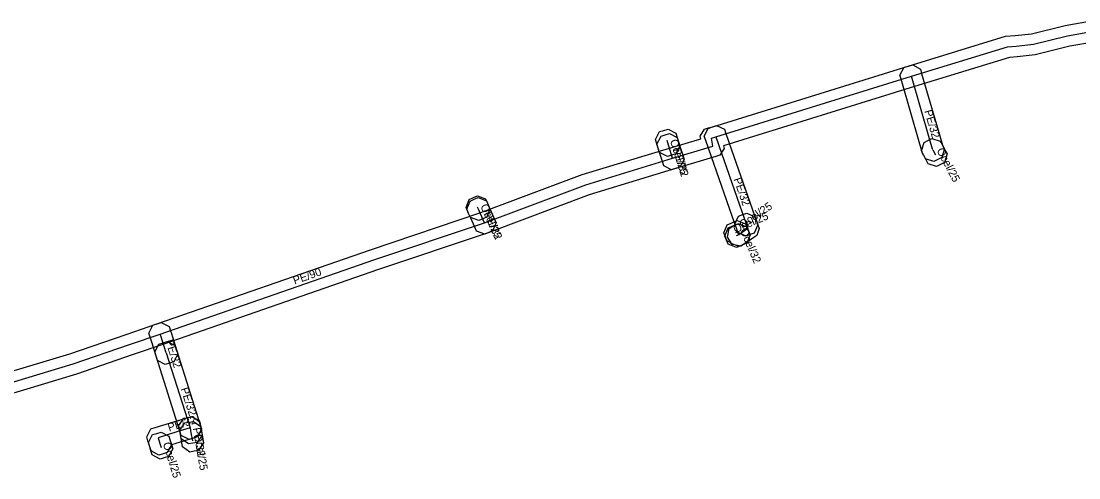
# Model space of a CAD drawing. Extents: x -677728 to -676939, y -1057290 to -1056960.
# Drawn here: x -677236.2 to -677137.1, y -1057070.2 to -1057027.4 of the extents above; entities that cross this region are included whole.
import ezdxf

# ---------------------------------------------------------------- set-up
doc = ezdxf.new("R2010")
doc.units = 0
for name, color, linetype in [('1', 7, 'Continuous'), ('24', 7, 'Continuous'), ('30', 7, 'Continuous')]:
    doc.layers.add(name, color=color, linetype=linetype)

msp = doc.modelspace()

# ---------------------------------------------------------------- linework, layer by layer
at = {"layer": '1'}
for points in [[(-677241.568, -1057061.585), (-677231.637, -1057058.588), (-677226.354, -1057056.778), (-677223.486, -1057055.795), (-677203.454, -1057048.844), (-677193.105, -1057045.358), (-677183.602, -1057041.793), (-677175.429, -1057039.303), (-677172.503, -1057038.428), (-677172.549, -1057038.178), (-677172.141, -1057037.524), (-677171.771, -1057037.418), (-677171.366, -1057037.302), (-677153.045, -1057031.614), (-677143.935, -1057028.821), (-677143.012, -1057028.754), (-677141.496, -1057028.584), (-677138.326, -1057027.801), (-677136.045, -1057027.397)], [(-677135.673, -1057029.363), (-677137.912, -1057029.759), (-677141.144, -1057030.556), (-677142.828, -1057030.746), (-677143.565, -1057030.799), (-677152.455, -1057033.526), (-677170.353, -1057039.081), (-677170.308, -1057039.328), (-677170.708, -1057039.979), (-677171.074, -1057040.088), (-677174.851, -1057041.217), (-677182.958, -1057043.687), (-677192.435, -1057047.242), (-677202.806, -1057050.736), (-677222.834, -1057057.685), (-677225.706, -1057058.67), (-677231.023, -1057060.492), (-677240.972, -1057063.495)]]:
    msp.add_lwpolyline(points, dxfattribs=at)
for points in [[(-677150.089, -1057038.166), (-677149.839, -1057039.032), (-677149.656, -1057039.379), (-677149.9, -1057040.171), (-677150.266, -1057040.364), (-677150.632, -1057040.557), (-677151.424, -1057040.313), (-677151.617, -1057039.947), (-677151.702, -1057039.787), (-677152.011, -1057038.722), (-677153.711, -1057032.848), (-677153.826, -1057032.45), (-677153.426, -1057031.724), (-677153.028, -1057031.609), (-677152.63, -1057031.494), (-677151.904, -1057031.894), (-677151.789, -1057032.292)], [(-677170.271, -1057037.541), (-677170.135, -1057037.932), (-677169.605, -1057039.456), (-677167.459, -1057045.632), (-677167.275, -1057046.126), (-677167.131, -1057046.515), (-677167.477, -1057047.268), (-677167.865, -1057047.412), (-677168.254, -1057047.556), (-677169.007, -1057047.21), (-677169.151, -1057046.822), (-677169.341, -1057046.308), (-677171.495, -1057040.112), (-677172.025, -1057038.588), (-677172.161, -1057038.197), (-677171.799, -1057037.451), (-677171.408, -1057037.315), (-677171.017, -1057037.179)], [(-677176.358, -1057039.713), (-677176.481, -1057039.318), (-677176.614, -1057038.893), (-677176.738, -1057038.497), (-677176.354, -1057037.763), (-677175.959, -1057037.64), (-677175.563, -1057037.516), (-677174.829, -1057037.9), (-677174.706, -1057038.295), (-677174.573, -1057038.72), (-677174.449, -1057039.116), (-677174.833, -1057039.85), (-677175.228, -1057039.973), (-677175.624, -1057040.097)], [(-677175.972, -1057040.953), (-677176.095, -1057040.558), (-677176.416, -1057039.528), (-677176.481, -1057039.318), (-677176.605, -1057038.922), (-677176.221, -1057038.188), (-677175.826, -1057038.065), (-677175.43, -1057037.941), (-677174.696, -1057038.325), (-677174.573, -1057038.72), (-677174.506, -1057038.932), (-677174.185, -1057039.962), (-677174.062, -1057040.358), (-677174.447, -1057041.092), (-677174.842, -1057041.215), (-677175.238, -1057041.338)], [(-677150.039, -1057038.65), (-677149.847, -1057039.017), (-677149.601, -1057039.488), (-677149.409, -1057039.855), (-677149.657, -1057040.645), (-677150.024, -1057040.837), (-677150.391, -1057041.029), (-677151.181, -1057040.781), (-677151.373, -1057040.414), (-677151.619, -1057039.943), (-677151.811, -1057039.576), (-677151.563, -1057038.786), (-677151.196, -1057038.594), (-677150.829, -1057038.402)], [(-677194.086, -1057045.803), (-677194.253, -1057045.424), (-677194.324, -1057045.263), (-677194.491, -1057044.884), (-677194.192, -1057044.111), (-677193.813, -1057043.944), (-677193.434, -1057043.777), (-677192.661, -1057044.076), (-677192.494, -1057044.455), (-677192.423, -1057044.616), (-677192.256, -1057044.995), (-677192.555, -1057045.768), (-677192.934, -1057045.935), (-677193.313, -1057046.102)], [(-677193.516, -1057047.084), (-677193.684, -1057046.705), (-677194.052, -1057045.876), (-677194.252, -1057045.426), (-677194.42, -1057045.047), (-677194.123, -1057044.274), (-677193.744, -1057044.106), (-677193.365, -1057043.938), (-677192.592, -1057044.235), (-677192.424, -1057044.614), (-677192.224, -1057045.064), (-677191.856, -1057045.895), (-677191.688, -1057046.274), (-677191.986, -1057047.046), (-677192.365, -1057047.214), (-677192.744, -1057047.382)], [(-677169.697, -1057048.223), (-677169.734, -1057048.137), (-677170.009, -1057048.025), (-677170.171, -1057047.644), (-677170.333, -1057047.263), (-677170.021, -1057046.495), (-677169.64, -1057046.333), (-677169.449, -1057046.252), (-677169.068, -1057046.091), (-677168.302, -1057046.4), (-677168.14, -1057046.78), (-677168.022, -1057047.056), (-677167.859, -1057047.437), (-677168.167, -1057048.205), (-677168.548, -1057048.368), (-677168.929, -1057048.531)], [(-677169.501, -1057046.621), (-677169.281, -1057046.472), (-677169.295, -1057046.433), (-677168.949, -1057045.68), (-677168.56, -1057045.536), (-677168.172, -1057045.392), (-677167.419, -1057045.738), (-677167.275, -1057046.127), (-677167.132, -1057046.513), (-677167.012, -1057046.837), (-677167.224, -1057047.495), (-677167.51, -1057047.688), (-677168.381, -1057048.277), (-677168.724, -1057048.509), (-677169.537, -1057048.352), (-677169.769, -1057048.009), (-677170.001, -1057047.666), (-677169.844, -1057046.853)], [(-677168.166, -1057048.205), (-677168.547, -1057048.368), (-677168.771, -1057048.464), (-677169.152, -1057048.627), (-677169.921, -1057048.32), (-677170.084, -1057047.939), (-677170.247, -1057047.558), (-677169.94, -1057046.789), (-677169.559, -1057046.626), (-677169.335, -1057046.53), (-677168.954, -1057046.367), (-677168.185, -1057046.674), (-677168.022, -1057047.055), (-677167.859, -1057047.436)], [(-677223.423, -1057059.213), (-677223.549, -1057058.818), (-677223.931, -1057057.615), (-677224.027, -1057057.314), (-677224.113, -1057057.042), (-677224.239, -1057056.647), (-677223.857, -1057055.912), (-677223.462, -1057055.787), (-677223.067, -1057055.661), (-677222.332, -1057056.043), (-677222.207, -1057056.438), (-677222.121, -1057056.708), (-677222.025, -1057057.009), (-677221.643, -1057058.212), (-677221.517, -1057058.607), (-677221.898, -1057059.342), (-677222.293, -1057059.468), (-677222.688, -1057059.594)], [(-677221.769, -1057057.817), (-677221.643, -1057058.212), (-677219.407, -1057065.247), (-677219.281, -1057065.642), (-677219.662, -1057066.377), (-677220.057, -1057066.503), (-677220.452, -1057066.629), (-677221.187, -1057066.248), (-677221.313, -1057065.853), (-677223.549, -1057058.818), (-677223.675, -1057058.423), (-677223.294, -1057057.688), (-677222.899, -1057057.562), (-677222.504, -1057057.436)], [(-677221.298, -1057066.886), (-677222.123, -1057067.141), (-677222.502, -1057067.852), (-677222.898, -1057067.973), (-677223.294, -1057068.094), (-677224.026, -1057067.704), (-677224.147, -1057067.308), (-677224.312, -1057066.767), (-677224.432, -1057066.371), (-677224.045, -1057065.641), (-677223.65, -1057065.52), (-677221.888, -1057064.976), (-677220.655, -1057064.595), (-677220.259, -1057064.472), (-677219.527, -1057064.859), (-677219.405, -1057065.255), (-677219.282, -1057065.651), (-677219.669, -1057066.383), (-677220.065, -1057066.505)], [(-677219.446, -1057064.971), (-677219.375, -1057065.379), (-677219.297, -1057065.828), (-677219.226, -1057066.236), (-677219.703, -1057066.913), (-677220.111, -1057066.984), (-677220.519, -1057067.055), (-677221.196, -1057066.578), (-677221.267, -1057066.17), (-677221.345, -1057065.721), (-677221.416, -1057065.313), (-677220.939, -1057064.636), (-677220.531, -1057064.565), (-677220.123, -1057064.494)], [(-677219.368, -1057065.42), (-677219.297, -1057065.828), (-677219.166, -1057066.581), (-677219.095, -1057066.989), (-677219.572, -1057067.666), (-677219.98, -1057067.737), (-677220.388, -1057067.808), (-677221.065, -1057067.331), (-677221.136, -1057066.923), (-677221.267, -1057066.17), (-677221.338, -1057065.762), (-677220.861, -1057065.085), (-677220.453, -1057065.014), (-677220.045, -1057064.943)], [(-677222.355, -1057066.327), (-677222.234, -1057066.723), (-677222.118, -1057067.101), (-677221.997, -1057067.497), (-677222.385, -1057068.229), (-677222.781, -1057068.35), (-677223.177, -1057068.471), (-677223.909, -1057068.083), (-677224.03, -1057067.687), (-677224.146, -1057067.309), (-677224.267, -1057066.913), (-677223.879, -1057066.181), (-677223.483, -1057066.06), (-677223.087, -1057065.939)]]:
    msp.add_lwpolyline(points, close=True, dxfattribs=at)
at = {"layer": '24'}
for points in [[(-677241.27, -1057062.54), (-677231.33, -1057059.54), (-677226.03, -1057057.724), (-677223.16, -1057056.74), (-677203.13, -1057049.79), (-677192.77, -1057046.3), (-677183.28, -1057042.74), (-677175.14, -1057040.26), (-677171.36, -1057039.13), (-677171.496, -1057038.379), (-677171.08, -1057038.26), (-677152.75, -1057032.57), (-677143.75, -1057029.81), (-677142.92, -1057029.75), (-677141.32, -1057029.57), (-677138.119, -1057028.78), (-677135.859, -1057028.38)], [(-677150.733, -1057039.48), (-677150.77, -1057039.41), (-677151.05, -1057038.444), (-677152.75, -1057032.57)], [(-677175.527, -1057039.019), (-677175.66, -1057038.594)], [(-677175.14, -1057040.26), (-677175.461, -1057039.23), (-677175.527, -1057039.019)], [(-677171.08, -1057038.26), (-677170.55, -1057039.784), (-677168.4, -1057045.97), (-677168.213, -1057046.474)], [(-677150.733, -1057039.48), (-677150.487, -1057039.951)], [(-677193.338, -1057045.02), (-677193.409, -1057044.859)], [(-677192.77, -1057046.3), (-677193.138, -1057045.47), (-677193.338, -1057045.02)], [(-677168.213, -1057046.474), (-677168.07, -1057046.86), (-677168.941, -1057047.449)], [(-677168.941, -1057047.449), (-677169.059, -1057047.173), (-677169.25, -1057047.254)], [(-677168.941, -1057047.449), (-677169.165, -1057047.545)], [(-677222.596, -1057058.515), (-677222.978, -1057057.312), (-677223.074, -1057057.011), (-677223.16, -1057056.74)], [(-677222.596, -1057058.515), (-677220.36, -1057065.55)], [(-677220.36, -1057065.55), (-677221.593, -1057065.931), (-677223.355, -1057066.475), (-677223.19, -1057067.016)], [(-677220.36, -1057065.55), (-677220.282, -1057065.999)], [(-677220.282, -1057065.999), (-677220.151, -1057066.752)], [(-677223.19, -1057067.016), (-677223.074, -1057067.394)]]:
    msp.add_lwpolyline(points, dxfattribs=at)

# ---------------------------------------------------------------- texts
at = {"layer": '30'}
for s, rotation, p in [('PE/32', 286.14102, (-677151.549, -1057035.828)), ('Ocel/25', 287.37705, (-677175.394, -1057038.606)), ('PE/32', 287.30967, (-677175.133, -1057039.439)), ('Ocel/25', 297.57775, (-677150.41, -1057039.515)), ('PE/32', 289.16536, (-677169.435, -1057042.216)), ('Ocel/25', 293.79718, (-677193.174, -1057044.74)), ('Ocel/25', 34.0679, (-677168.576, -1057046.867)), ('PE/32', 293.91123, (-677192.854, -1057045.46)), ('Ocel/25', 23.19859, (-677169.253, -1057047.297)), ('Ocel/32', 293.14846, (-677168.841, -1057047.016)), ('PE/90', 19.13573, (-677210.564, -1057052.1)), ('PE/32', 287.6167, (-677222.693, -1057057.38)), ('PE/32', 287.63231, (-677221.263, -1057061.88)), ('PE/32', 17.15755, (-677222.328, -1057065.896)), ('PE/32', 279.85504, (-677220.121, -1057065.575)), ('Ocel/25', 287.06011, (-677222.932, -1057067.005)), ('Ocel/25', 279.86902, (-677220.017, -1057066.176))]:
    msp.add_text(s, height=0.75, rotation=rotation, dxfattribs=at).set_placement(p)

doc.saveas('drawing.dxf')
